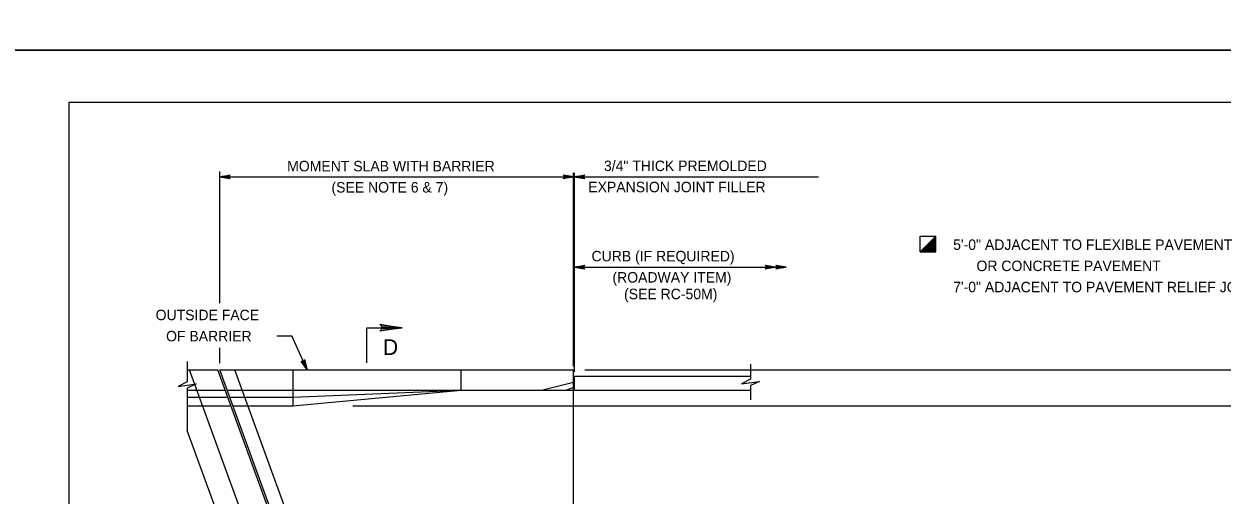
# Model space of a CAD drawing. Extents: x 636530 to 644067, y 294168 to 299122.
# Drawn here: x 639033.9 to 639377.3, y 298199 to 298334 of the extents above; entities that cross this region are included whole.
import ezdxf

# ---------------------------------------------------------------- set-up
doc = ezdxf.new("R2010")
doc.units = 0
doc.layers.add('1', color=7, linetype='Continuous')
doc.layers.add('PLT-BNDY', color=7, linetype='Continuous')

msp = doc.modelspace()

# ---------------------------------------------------------------- linework, layer by layer
at = {"layer": '1'}
for p, q in [((639832.78, 298311.48), (639046.78, 298311.48)), ((639046.78, 298311.48), (639046.78, 297747.48)), ((639090.04, 298253.99), (639090.04, 298291.73)), ((639090.04, 298290.19), (639191.45, 298290.19)), ((639191.45, 298235.81), (639191.45, 298291.32)), ((639191.71, 298234.26), (639191.71, 298291.32)), ((639191.71, 298290.19), (639261.61, 298290.19)), ((639290.76, 298273.22), (639295.33, 298273.22)), ((639290.76, 298268.65), (639290.76, 298273.22)), ((639295.33, 298273.22), (639290.76, 298268.65)), ((639295.33, 298273.15), (639290.83, 298268.65)), ((639295.33, 298273.09), (639290.89, 298268.65)), ((639295.33, 298273.02), (639290.95, 298268.65)), ((639295.33, 298272.96), (639291.02, 298268.65)), ((639295.33, 298272.9), (639291.08, 298268.65)), ((639295.33, 298272.83), (639291.15, 298268.65)), ((639295.33, 298272.77), (639291.21, 298268.65)), ((639295.33, 298272.7), (639291.28, 298268.65)), ((639295.33, 298272.64), (639291.34, 298268.65)), ((639295.33, 298272.57), (639291.41, 298268.65)), ((639295.33, 298272.51), (639291.47, 298268.65)), ((639295.33, 298272.44), (639291.54, 298268.65)), ((639295.33, 298272.38), (639291.6, 298268.65)), ((639295.33, 298272.31), (639291.67, 298268.65)), ((639295.33, 298272.25), (639291.73, 298268.65)), ((639295.33, 298272.18), (639291.8, 298268.65)), ((639295.33, 298272.12), (639291.86, 298268.65)), ((639295.33, 298272.05), (639291.92, 298268.65)), ((639295.33, 298268.65), (639295.33, 298273.22)), ((639290.76, 298268.65), (639295.33, 298268.65)), ((639295.33, 298271.99), (639291.99, 298268.65)), ((639295.33, 298271.93), (639292.05, 298268.65)), ((639295.33, 298271.86), (639292.12, 298268.65)), ((639295.33, 298271.8), (639292.18, 298268.65)), ((639295.33, 298271.73), (639292.25, 298268.65)), ((639295.33, 298271.67), (639292.31, 298268.65)), ((639295.33, 298271.6), (639292.38, 298268.65)), ((639295.33, 298271.54), (639292.44, 298268.65)), ((639295.33, 298271.47), (639292.51, 298268.65)), ((639295.33, 298271.41), (639292.57, 298268.65)), ((639295.33, 298271.34), (639292.64, 298268.65)), ((639295.33, 298271.28), (639292.7, 298268.65)), ((639295.33, 298271.21), (639292.76, 298268.65)), ((639295.33, 298271.15), (639292.83, 298268.65)), ((639295.33, 298271.08), (639292.89, 298268.65)), ((639295.33, 298271.02), (639292.96, 298268.65)), ((639295.33, 298270.96), (639293.02, 298268.65)), ((639295.33, 298270.89), (639293.09, 298268.65)), ((639295.33, 298270.83), (639293.15, 298268.65)), ((639295.33, 298270.76), (639293.22, 298268.65)), ((639295.33, 298270.7), (639293.28, 298268.65)), ((639295.33, 298270.63), (639293.35, 298268.65)), ((639295.33, 298270.57), (639293.41, 298268.65)), ((639295.33, 298270.5), (639293.48, 298268.65)), ((639295.33, 298270.44), (639293.54, 298268.65)), ((639295.33, 298270.37), (639293.61, 298268.65)), ((639295.33, 298270.31), (639293.67, 298268.65)), ((639295.33, 298270.24), (639293.73, 298268.65)), ((639295.33, 298270.18), (639293.8, 298268.65)), ((639295.33, 298270.11), (639293.86, 298268.65)), ((639295.33, 298270.05), (639293.93, 298268.65)), ((639295.33, 298269.99), (639293.99, 298268.65)), ((639295.33, 298269.92), (639294.06, 298268.65)), ((639295.33, 298269.86), (639294.12, 298268.65)), ((639295.33, 298269.79), (639294.19, 298268.65)), ((639295.33, 298269.73), (639294.25, 298268.65)), ((639295.33, 298269.66), (639294.32, 298268.65)), ((639295.33, 298269.6), (639294.38, 298268.65)), ((639295.33, 298269.53), (639294.45, 298268.65)), ((639295.33, 298269.47), (639294.51, 298268.65)), ((639295.33, 298269.4), (639294.58, 298268.65)), ((639295.33, 298269.34), (639294.64, 298268.65)), ((639295.33, 298269.27), (639294.7, 298268.65)), ((639295.33, 298269.21), (639294.77, 298268.65)), ((639295.33, 298269.15), (639294.83, 298268.65)), ((639295.33, 298269.08), (639294.9, 298268.65)), ((639295.33, 298269.02), (639294.96, 298268.65)), ((639295.33, 298268.95), (639295.03, 298268.65)), ((639295.33, 298268.89), (639295.09, 298268.65)), ((639295.33, 298268.82), (639295.16, 298268.65)), ((639295.33, 298268.76), (639295.22, 298268.65)), ((639295.33, 298268.69), (639295.29, 298268.65)), ((639191.71, 298264.27), (639252.41, 298264.27)), ((639106.41, 298244.64), (639110.72, 298244.64)), ((639115.07, 298234.88), (639110.72, 298244.64)), ((639090.04, 298236.8), (639090.04, 298241.23)), ((639080.72, 298237.23), (639080.72, 298231.42)), ((639080.72, 298234.88), (639089.5, 298234.88)), ((639153.09, 298037.91), (639081.39, 298234.88)), ((639161.71, 298036.49), (639089.5, 298234.88)), ((639090.04, 298234.88), (639191.45, 298234.88)), ((639186.28, 297970.47), (639090.04, 298234.88)), ((639190.61, 297970.47), (639094.37, 298234.88)), ((639110.93, 298234.88), (639110.93, 298224.6)), ((639159.21, 298229.02), (639159.21, 298234.88)), ((639191.45, 298175.83), (639191.45, 298234.88)), ((639194.64, 298234.88), (639220.98, 298234.88)), ((639220.98, 298234.88), (639501.47, 298234.88)), ((639242.2, 298236.53), (639242.2, 298232.17)), ((639191.45, 298231.23), (639182.59, 298229.02)), ((639191.71, 298233.08), (639242.2, 298233.08)), ((639191.71, 298229.02), (639191.71, 298233.08)), ((639080.72, 298229.62), (639080.72, 298217.48)), ((639080.72, 298229.02), (639091.64, 298229.02)), ((639092.18, 298229.02), (639159.21, 298229.02)), ((639110.93, 298227.07), (639159.21, 298229.02)), ((639110.93, 298224.6), (639159.21, 298229.02)), ((639159.21, 298229.02), (639191.45, 298229.02)), ((639191.45, 298229.77), (639189.44, 298229.02)), ((639191.71, 298229.02), (639242.2, 298229.02)), ((639242.2, 298230.36), (639242.2, 298226.3)), ((639080.72, 298227.07), (639092.35, 298227.07)), ((639080.72, 298224.6), (639093.25, 298224.6)), ((639092.89, 298227.07), (639110.93, 298227.07)), ((639093.79, 298224.6), (639110.93, 298224.6)), ((639128.18, 298224.6), (639452.04, 298224.6)), ((639096.89, 298173.06), (639080.72, 298217.48))]:
    msp.add_line(p, q, dxfattribs=at)
for points in [[(639090.04, 298290.19), (639093.03, 298290.75), (639092.91, 298290.67), (639092.8, 298290.59), (639092.74, 298290.49), (639092.68, 298290.39), (639092.66, 298290.29), (639092.64, 298290.19), (639092.66, 298290.09), (639092.68, 298289.99), (639092.74, 298289.89), (639092.8, 298289.79), (639092.91, 298289.71), (639093.03, 298289.63), (639090.04, 298290.19), (639092.91, 298289.71), (639092.8, 298289.79), (639090.04, 298290.19), (639092.74, 298289.89), (639092.68, 298289.99), (639090.04, 298290.19), (639092.66, 298290.09), (639092.64, 298290.19), (639090.04, 298290.19), (639092.66, 298290.29), (639092.68, 298290.39), (639090.04, 298290.19), (639092.74, 298290.49), (639092.8, 298290.59), (639090.04, 298290.19), (639092.91, 298290.67)], [(639191.45, 298290.19), (639188.47, 298289.63), (639188.58, 298289.71), (639188.7, 298289.79), (639188.76, 298289.89), (639188.82, 298289.99), (639188.83, 298290.09), (639188.85, 298290.19), (639188.83, 298290.29), (639188.82, 298290.39), (639188.76, 298290.49), (639188.7, 298290.59), (639188.58, 298290.67), (639188.47, 298290.75), (639191.45, 298290.19), (639188.58, 298290.67), (639188.7, 298290.59), (639191.45, 298290.19), (639188.76, 298290.49), (639188.82, 298290.39), (639191.45, 298290.19), (639188.83, 298290.29), (639188.85, 298290.19), (639191.45, 298290.19), (639188.83, 298290.09), (639188.82, 298289.99), (639191.45, 298290.19), (639188.76, 298289.89), (639188.7, 298289.79), (639191.45, 298290.19), (639188.58, 298289.71)], [(639191.71, 298290.19), (639194.69, 298290.75), (639194.57, 298290.67), (639194.46, 298290.59), (639194.4, 298290.49), (639194.34, 298290.39), (639194.32, 298290.29), (639194.31, 298290.19), (639194.32, 298290.09), (639194.34, 298289.99), (639194.4, 298289.89), (639194.46, 298289.79), (639194.57, 298289.71), (639194.69, 298289.63), (639191.71, 298290.19), (639194.57, 298289.71), (639194.46, 298289.79), (639191.71, 298290.19), (639194.4, 298289.89), (639194.34, 298289.99), (639191.71, 298290.19), (639194.32, 298290.09), (639194.31, 298290.19), (639191.71, 298290.19), (639194.32, 298290.29), (639194.34, 298290.39), (639191.71, 298290.19), (639194.4, 298290.49), (639194.46, 298290.59), (639191.71, 298290.19), (639194.57, 298290.67)], [(639191.71, 298264.27), (639194.69, 298264.83), (639194.57, 298264.75), (639194.46, 298264.67), (639194.4, 298264.57), (639194.34, 298264.47), (639194.32, 298264.37), (639194.31, 298264.27), (639194.32, 298264.17), (639194.34, 298264.07), (639194.4, 298263.97), (639194.46, 298263.87), (639194.57, 298263.79), (639194.69, 298263.71), (639191.71, 298264.27), (639194.57, 298263.79), (639194.46, 298263.87), (639191.71, 298264.27), (639194.4, 298263.97), (639194.34, 298264.07), (639191.71, 298264.27), (639194.32, 298264.17), (639194.31, 298264.27), (639191.71, 298264.27), (639194.32, 298264.37), (639194.34, 298264.47), (639191.71, 298264.27), (639194.4, 298264.57), (639194.46, 298264.67), (639191.71, 298264.27), (639194.57, 298264.75)], [(639249.36, 298264.27), (639246.38, 298263.71), (639246.5, 298263.79), (639246.61, 298263.87), (639246.67, 298263.97), (639246.73, 298264.07), (639246.75, 298264.17), (639246.76, 298264.27), (639246.75, 298264.37), (639246.73, 298264.47), (639246.67, 298264.57), (639246.61, 298264.67), (639246.5, 298264.75), (639246.38, 298264.83), (639249.36, 298264.27), (639246.5, 298264.75), (639246.61, 298264.67), (639249.36, 298264.27), (639246.67, 298264.57), (639246.73, 298264.47), (639249.36, 298264.27), (639246.75, 298264.37), (639246.76, 298264.27), (639249.36, 298264.27), (639246.75, 298264.17), (639246.73, 298264.07), (639249.36, 298264.27), (639246.67, 298263.97), (639246.61, 298263.87), (639249.36, 298264.27), (639246.5, 298263.79)], [(639252.41, 298264.27), (639249.43, 298263.71), (639249.54, 298263.79), (639249.66, 298263.87), (639249.72, 298263.97), (639249.78, 298264.07), (639249.79, 298264.17), (639249.81, 298264.27), (639249.79, 298264.37), (639249.78, 298264.47), (639249.72, 298264.57), (639249.66, 298264.67), (639249.54, 298264.75), (639249.43, 298264.83), (639252.41, 298264.27), (639249.54, 298264.75), (639249.66, 298264.67), (639252.41, 298264.27), (639249.72, 298264.57), (639249.78, 298264.47), (639252.41, 298264.27), (639249.79, 298264.37), (639249.81, 298264.27), (639252.41, 298264.27), (639249.79, 298264.17), (639249.78, 298264.07), (639252.41, 298264.27), (639249.72, 298263.97), (639249.66, 298263.87), (639252.41, 298264.27), (639249.54, 298263.79)], [(639136.18, 298247.72), (639136.41, 298247.28), (639142.28, 298246.95), (639136.18, 298247.72), (639135.87, 298247.99), (639142.28, 298246.95), (639136.41, 298246.66), (639136.2, 298246.22), (639142.28, 298246.95), (639135.87, 298245.93), (639136.2, 298246.22)], [(639132.2, 298236.87), (639132.2, 298246.95), (639142.28, 298246.95)], [(639115.07, 298234.88), (639113.34, 298237.38), (639113.46, 298237.31), (639113.58, 298237.24), (639113.7, 298237.22), (639113.81, 298237.21), (639113.91, 298237.23), (639114.01, 298237.26), (639114.09, 298237.31), (639114.18, 298237.37), (639114.24, 298237.47), (639114.31, 298237.56), (639114.34, 298237.7), (639114.36, 298237.84), (639115.07, 298234.88), (639114.34, 298237.7), (639114.31, 298237.56), (639115.07, 298234.88), (639114.24, 298237.47), (639114.18, 298237.37), (639115.07, 298234.88), (639114.09, 298237.31), (639114.01, 298237.26), (639115.07, 298234.88), (639113.91, 298237.23), (639113.81, 298237.21), (639115.07, 298234.88), (639113.7, 298237.22), (639113.58, 298237.24), (639115.07, 298234.88), (639113.46, 298237.31)], [(639080.72, 298231.42), (639078.07, 298230.13), (639083.26, 298230.83), (639080.72, 298229.62)], [(639242.2, 298232.17), (639239.54, 298230.87), (639244.74, 298231.57), (639242.2, 298230.36)]]:
    msp.add_lwpolyline(points, dxfattribs=at)
at = {"layer": 'PLT-BNDY'}
for points in [[(639006.78, 298920.48), (639847.78, 298920.48), (639847.78, 298326.48), (639006.78, 298326.48)], [(639006.78, 298326.48), (639847.78, 298326.48), (639847.78, 297732.48), (639006.78, 297732.48)]]:
    msp.add_lwpolyline(points, close=True, dxfattribs=at)

# ---------------------------------------------------------------- texts
at = {"layer": '1'}
for s, height, p in [('MOMENT SLAB WITH BARRIER', 3, (639109.35, 298291.75)), ('3/4" THICK PREMOLDED', 3, (639200.16, 298291.83)), ('(SEE NOTE 6 & 7)', 3, (639122.05, 298285.68)), ('EXPANSION JOINT FILLER', 3, (639195.66, 298285.76)), ('5\'-0" ADJACENT TO FLEXIBLE PAVEMENT', 3, (639300.25, 298269.24)), ('CURB (IF REQUIRED)', 3, (639196.59, 298265.96)), ('      OR CONCRETE PAVEMENT', 3, (639300.25, 298263.17)), ('(ROADWAY ITEM)', 3, (639202.59, 298259.88)), ('(SEE RC-50M)', 3, (639205.92, 298255.12)), ('7\'-0" ADJACENT TO PAVEMENT RELIEF JOINT', 3, (639300.25, 298257.1)), ('OUTSIDE FACE', 3, (639071.65, 298249.1)), ('OF BARRIER', 3, (639074.64, 298243.03)), ('D', 4.5, (639136.81, 298239.13))]:
    msp.add_text(s, height=height, dxfattribs=at).set_placement(p)

doc.saveas('drawing.dxf')
